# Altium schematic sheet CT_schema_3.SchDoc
size 577 x 383 mm
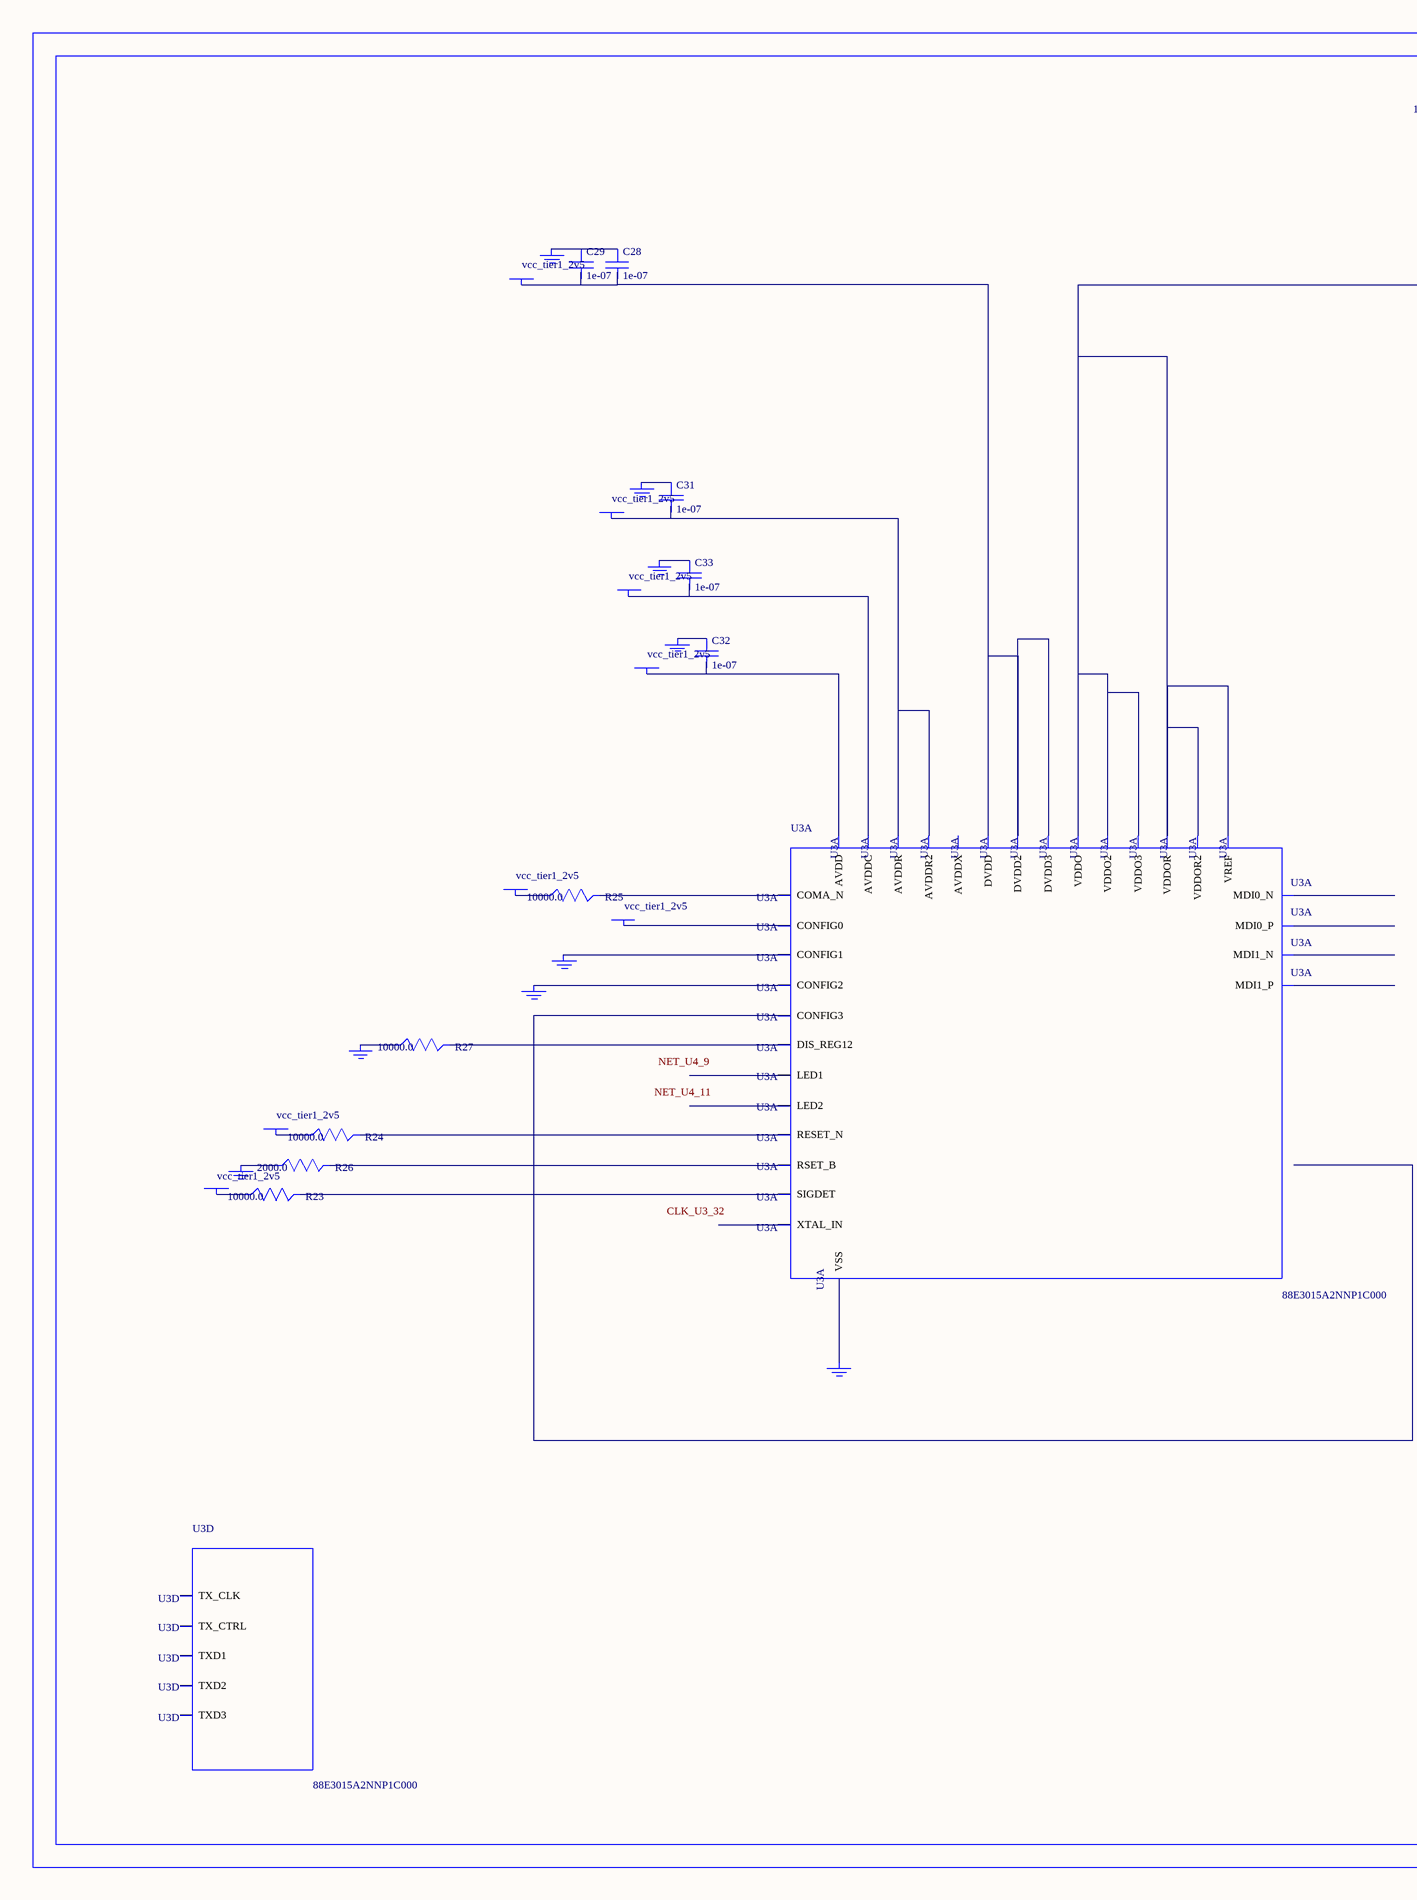
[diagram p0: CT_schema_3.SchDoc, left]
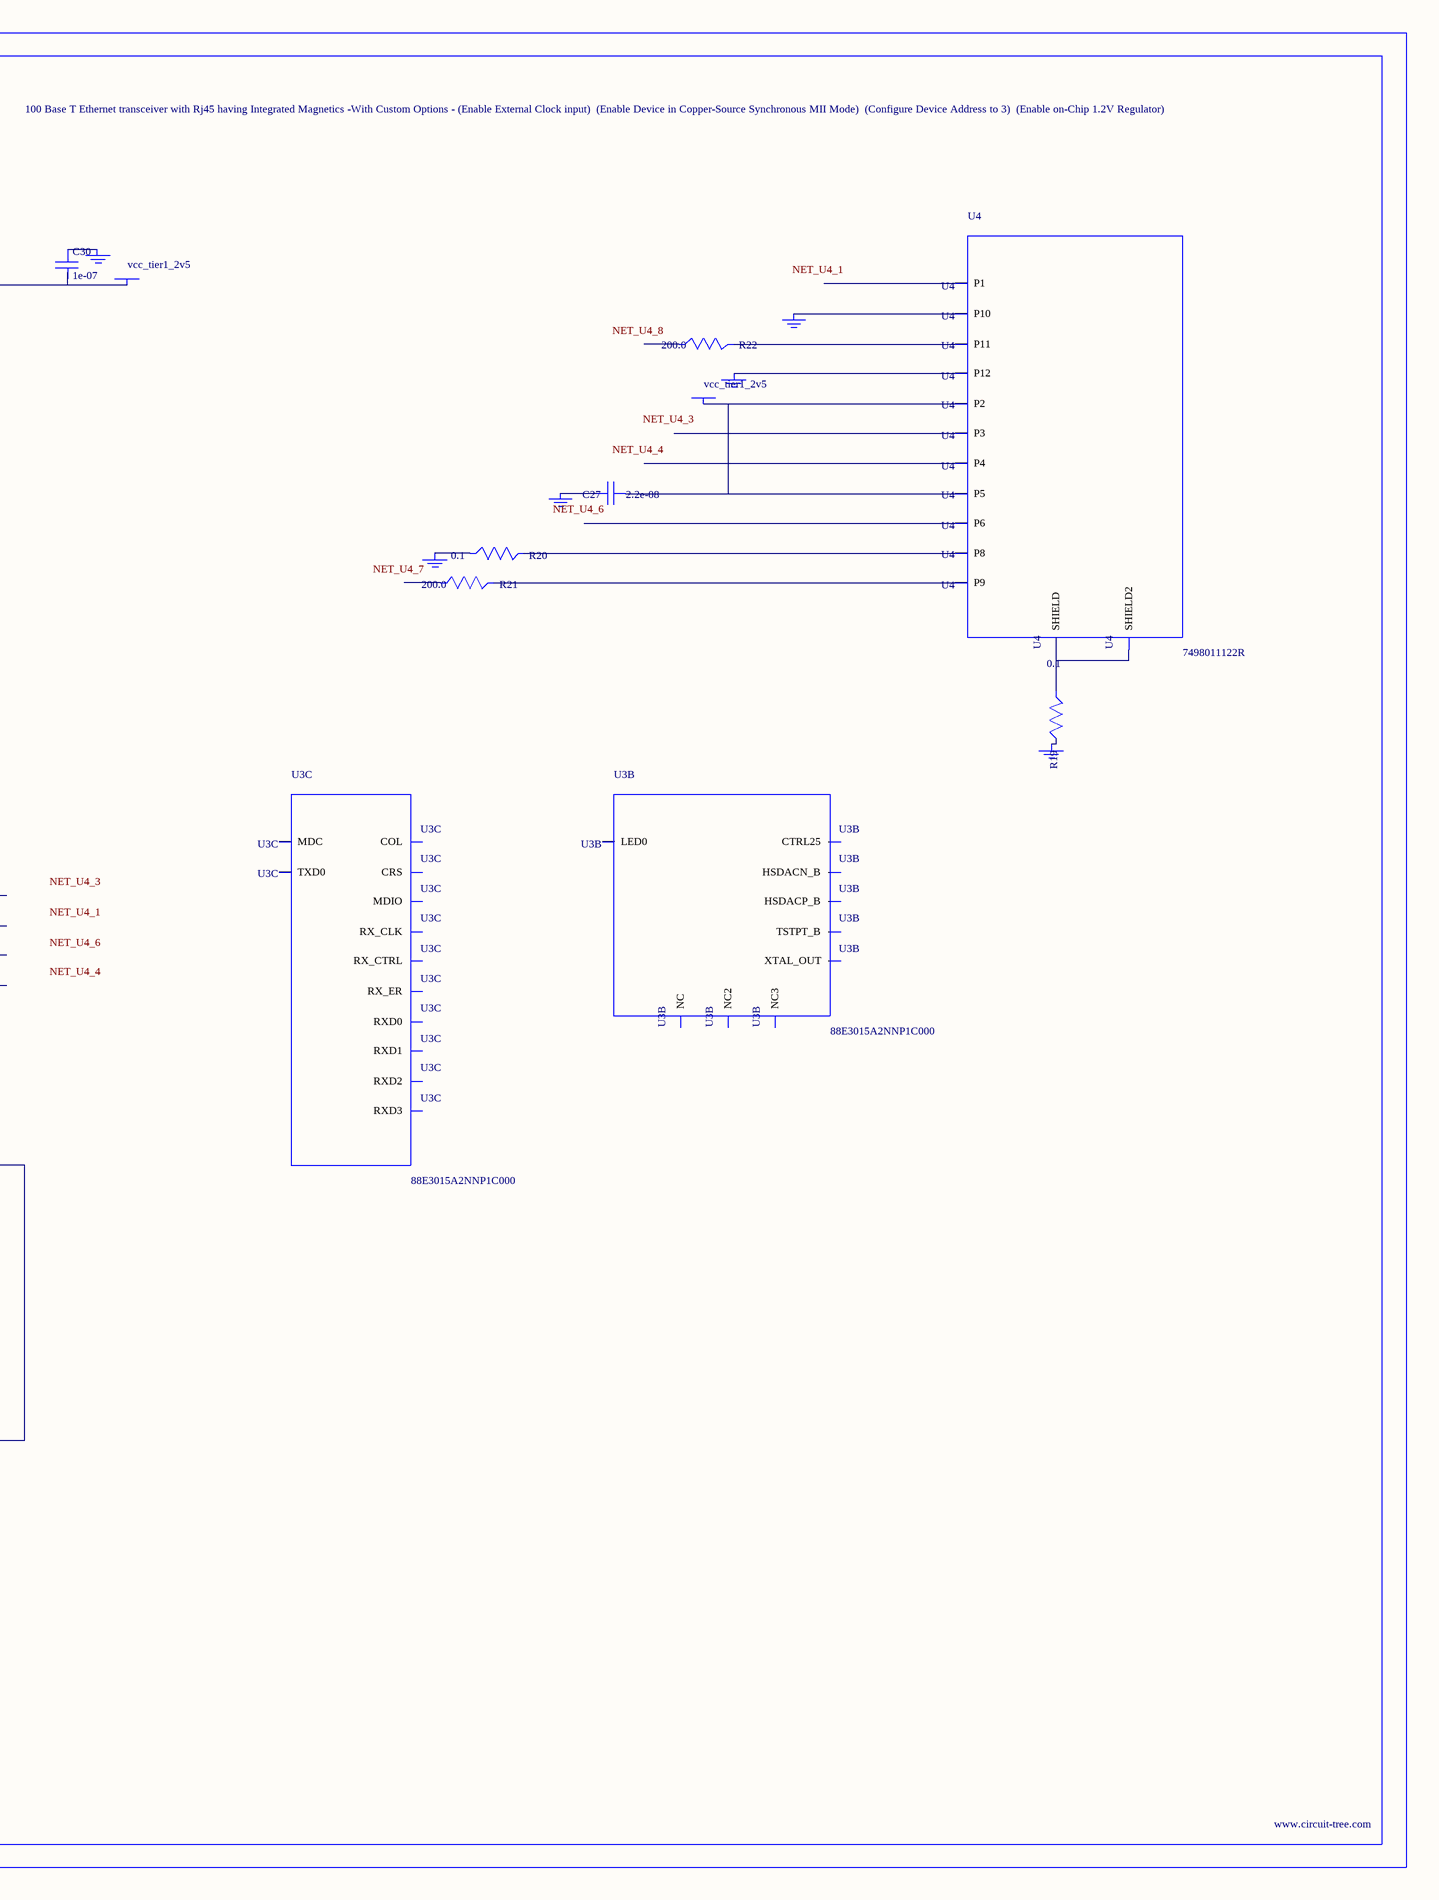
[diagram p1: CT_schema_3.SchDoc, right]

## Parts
BORDER2  (no value)
C27  2.2e-08  [C0402]
C28  1e-07  [C0603]
C29  1e-07  [C0603]
C30  1e-07  [C0603]
C31  1e-07  [C0603]
C32  1e-07  [C0603]
C33  1e-07  [C0603]
GND_INSTANCE_2_0  (no value)
GND_INSTANCE_2_1  (no value)
GND_INSTANCE_2_2  (no value)
GND_INSTANCE_2_3  (no value)
GND_INSTANCE_2_4  (no value)
GND_INSTANCE_2_5  (no value)
GND_INSTANCE_2_6  (no value)
GND_INSTANCE_2_7  (no value)
GND_INSTANCE_2_8  (no value)
GND_INSTANCE_2_9  (no value)
GND_INSTANCE_2_10  (no value)
GND_INSTANCE_2_11  (no value)
GND_INSTANCE_2_12  (no value)
GND_INSTANCE_2_13  (no value)
GND_INSTANCE_2_14  (no value)
POWER_INSTANCE_2_0  vcc_tier1_2v5
POWER_INSTANCE_2_1  vcc_tier1_2v5
POWER_INSTANCE_2_2  vcc_tier1_2v5
POWER_INSTANCE_2_3  vcc_tier1_2v5
POWER_INSTANCE_2_4  vcc_tier1_2v5
POWER_INSTANCE_2_5  vcc_tier1_2v5
POWER_INSTANCE_2_6  vcc_tier1_2v5
POWER_INSTANCE_2_7  vcc_tier1_2v5
POWER_INSTANCE_2_8  vcc_tier1_2v5
POWER_INSTANCE_2_9  vcc_tier1_2v5
R19  0.1  [R0603]
R20  0.1  [R0603]
R21  200.0  [R0603]
R22  200.0  [R0603]
R23  10000.0  [R0603]
R24  10000.0  [R0603]
R25  10000.0  [R0603]
R26  2000.0  [R0603]
R27  10000.0  [R0603]
U3  88E3015A2NNP1C000  [88E3015A2NNP1C000]  (parts A,B,C,D of 4)
U4  7498011122R  [7498011122R]

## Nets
NetC27_1: C27.1 POWER_INSTANCE_2_9.0(PWR) U4.2(P2) U4.5(P5)
NetC27_2: C27.2 GND_INSTANCE_2_10.0(GND)
NetC28_1: C28.1 C29.1 GND_INSTANCE_2_2.0(GND)
NetC28_2: C28.2 C29.2 POWER_INSTANCE_2_0.0(PWR) U3.4(DVDD) U3.11(DVDD2) U3.34(DVDD3)
NetC30_1: C30.1 GND_INSTANCE_2_3.0(GND)
NetC30_2: C30.2 POWER_INSTANCE_2_1.0(PWR) U3.6(VDDO) U3.20(VDDO2) U3.36(VDDO3) U3.44(VDDOR) U3.48(VDDOR2) U3.49(VREF)
NetC31_1: C31.1 GND_INSTANCE_2_5.0(GND)
NetC31_2: C31.2 POWER_INSTANCE_2_3.0(PWR) U3.12(AVDDR) U3.13(AVDDR2)
NetC32_1: C32.1 GND_INSTANCE_2_6.0(GND)
NetC32_2: C32.2 POWER_INSTANCE_2_5.0(PWR) U3.24(AVDD)
NetC33_1: C33.1 GND_INSTANCE_2_8.0(GND)
NetC33_2: C33.2 POWER_INSTANCE_2_6.0(PWR) U3.29(AVDDC)
NetGND_INSTANCE_2_0_0: GND_INSTANCE_2_0.0(GND) U3.1(CONFIG1)
NetGND_INSTANCE_2_1_0: GND_INSTANCE_2_1.0(GND) U3.2(CONFIG2)
NetGND_INSTANCE_2_4_0: GND_INSTANCE_2_4.0(GND) R27.1
NetGND_INSTANCE_2_7_0: GND_INSTANCE_2_7.0(GND) R26.1
NetGND_INSTANCE_2_9_0: GND_INSTANCE_2_9.0(GND) U3.57(VSS)
NetGND_INSTANCE_2_11_0: GND_INSTANCE_2_11.0(GND) R20.1
NetGND_INSTANCE_2_12_0: GND_INSTANCE_2_12.0(GND) U4.10(P10)
NetGND_INSTANCE_2_13_0: GND_INSTANCE_2_13.0(GND) U4.12(P12)
NetGND_INSTANCE_2_14_0: GND_INSTANCE_2_14.0(GND) R19.2
NetPOWER_INSTANCE_2_2_0: POWER_INSTANCE_2_2.0(PWR) R24.1
NetPOWER_INSTANCE_2_4_0: POWER_INSTANCE_2_4.0(PWR) R23.1
NetPOWER_INSTANCE_2_7_0: POWER_INSTANCE_2_7.0(PWR) R25.1
NetPOWER_INSTANCE_2_8_0: POWER_INSTANCE_2_8.0(PWR) U3.56(CONFIG0)
NetR19_1: R19.1 U4.13(SHIELD) U4.14(SHIELD2)
NetR20_2: R20.2 U4.8(P8)
NetR21_2: R21.2 U4.9(P9)
NetR22_2: R22.2 U4.11(P11)
NetR23_2: R23.2 U3.16(SIGDET)
NetR24_2: R24.2 U3.9(RESET_N)
NetR25_2: R25.2 U3.39(COMA_N)
NetR26_2: R26.2 U3.28(RSET_B)
NetR27_2: R27.2 U3.10(DIS_REG12)

Not connected (* = marked no-connect by the designer): R21 1; R22 1; U3 3(CONFIG3) 5(LED0) 7(LED1) 8(LED2) 14(AVDDX) 15(CTRL25) 17(RX_ER) 18(CRS) 19(COL) 21(NC) 22(MDI1_N) 23(MDI1_P) 25(MDI0_N) 26(MDI0_P) 27(TSTPT_B) 30(HSDACN_B) 31(HSDACP_B) 32(XTAL_IN) 33(XTAL_OUT) 35(MDIO) 37(NC2) 38(MDC) 40(NC3) 41(RX_CTRL) 42(RXD0) 43(RXD1) 45(RX_CLK) 46(RXD2) 47(RXD3) 50(TXD0) 51(TXD1) 52(TX_CLK) 53(TXD2) 54(TXD3) 55(TX_CTRL); U4 1(P1) 3(P3) 4(P4) 6(P6)

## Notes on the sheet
- Labels drawn without touching a wire or pin: CLK_U3_32, NET_U4_1, NET_U4_3, NET_U4_4, NET_U4_6, NET_U4_7, NET_U4_8, NET_U4_9, NET_U4_11

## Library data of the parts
BORDER2 = BORDER_PAGE2
C27 = C0402C223K3RAC
C28-C33 = 06035C104K4Z2A
GND_INSTANCE_2_0-GND_INSTANCE_2_14 = GND
POWER_INSTANCE_2_0-POWER_INSTANCE_2_9 = PWR
R19 R20 = ERJ-3RSFR10V
R21 R22 = RC0603JR-07200RL
R23-R25 R27 = RC0603JR-0710KL
R26 = RC0603JR-072KL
